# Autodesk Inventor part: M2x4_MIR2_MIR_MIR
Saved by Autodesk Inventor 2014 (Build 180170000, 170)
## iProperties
Created: 2015-05
Part Number: M2x4_MIR2_MIR_MIR
Material: 일반
Vendor: CBT Solutions
Document SubType Name: 모델링
Designer: Administrator
Appearance: 기본값
Company: 한국ATC센터
Author: KYOUNG IL JANG
Comments: 파생
d0: 1.000 ul
d0_1: 1.000 ul
d0_1_1: 1.000 ul
d0_1_1_1: 1.000 ul
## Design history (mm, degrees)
derived "M2x4_MIR2_MIR.ipt"
feature "솔리드1::M2x4_MIR2_MIR.ipt"
tag "피쳐 태그1"
node "솔리드1"
other parameters: "d0" = 1, "d0_1" = 1, "d0_1_1" = 1, "d0_1_1_1" = 1
